// TIA Portal project "SVC_Sample" (V13)

(* hardware
DEVICE "S7-1200-Station_1"  S7-1200 Station
   slot 0: "Baugruppenträger_0"  Rack  V1.0
   slot 1: "PLC_1"  CPU 1214C DC/DC/DC  6ES7 214-1AG40-0XB0  V4.1
DEVICE "S71500/ET200MP-Station_1"  S7-1500 station
   slot 0: "Profilschiene_0"  6ES7 590-1***0-0AA0
   slot 1: "PLC_2"  CPU 1513F-1 PN  6ES7 513-1FL00-0AB0  V1.7
DEVICE "GSD-Geraet_2"  GSD.Device.PN
   slot 0: "Baugruppenträger"  Rail  V1.0
   slot 0: "svc01"  BAE0103  V3.x
DEVICE "GSD-Geraet_1"  GSD.Device.PN
   slot 0: "Baugruppenträger"  Rail  V1.0
   slot 0: "svc01_1"  BAE0103  V3.x
*)

// ===== PLC "PLC_1"  CPU 1214C DC/DC/DC =====

VAR_GLOBAL   // PLC tag table "Standard-Variablentabelle"
   "System_Byte" AT %MB1 : Byte;
   "FirstScan" AT %M1.0 : Bool;
   "DiagStatusUpdate" AT %M1.1 : Bool;
   "AlwaysTRUE" AT %M1.2 : Bool;
   "AlwaysFALSE" AT %M1.3 : Bool;
   "Clock_Byte" AT %MB0 : Byte;
   "Clock_10Hz" AT %M0.0 : Bool;
   "Clock_5Hz" AT %M0.1 : Bool;
   "Clock_2.5Hz" AT %M0.2 : Bool;
   "Clock_2Hz" AT %M0.3 : Bool;
   "Clock_1.25Hz" AT %M0.4 : Bool;
   "Clock_1Hz" AT %M0.5 : Bool;
   "Clock_0.625Hz" AT %M0.6 : Bool;
   "Clock_0.5Hz" AT %M0.7 : Bool;
END_VAR

DATA_BLOCK "DB_BVS_SC"   // DB10
{ S7_Optimized_Access := 'FALSE' }
VERSION : 0.1
"Call_BVS_SC"
BEGIN
END_DATA_BLOCK

DATA_BLOCK "Cam_Input"   // DB31
{ S7_Optimized_Access := 'FALSE' }
VERSION : 0.1
   VAR
      SendByte : Array[0..3999] of Byte;
   END_VAR
BEGIN
END_DATA_BLOCK

DATA_BLOCK "Cam_Output"   // DB32
{ S7_Optimized_Access := 'FALSE' }
VERSION : 0.1
   VAR
      "n.u." : Byte;
      AppID : Byte;
      Brightness : Int;
      ReadBarcode : Array[0..255] of Char;
      CodePositionX : Real;
      BarcodeLocated : Byte;
   END_VAR
BEGIN
END_DATA_BLOCK

FUNCTION_BLOCK "Call_BVS_SC"   // FB10, FBD
TITLE = Calling example Smart Camera / Smart Vision Controller FB
{ S7_Optimized_Access := 'FALSE' }
VERSION : 0.1
// Example call for Smart Camera / Smart Vision Controller function block BVS_SC[FB50]
// ! Same functionblock FB 50 can be used for Smart Camera and Smart Vision Controller!
// 
// FB Inputs are assigned to static variables of "Call_BVS_SC[FB10]".
   VAR_TEMP   // added for the SCL form of the ladder/FBD networks
      _w1 : Bool;
   END_VAR
BEGIN

REGION Network 1: Set Defaults
   // Set the FB Inputs to default values 
   // The Cam_Default bit is set at PLC Startup [OB100].
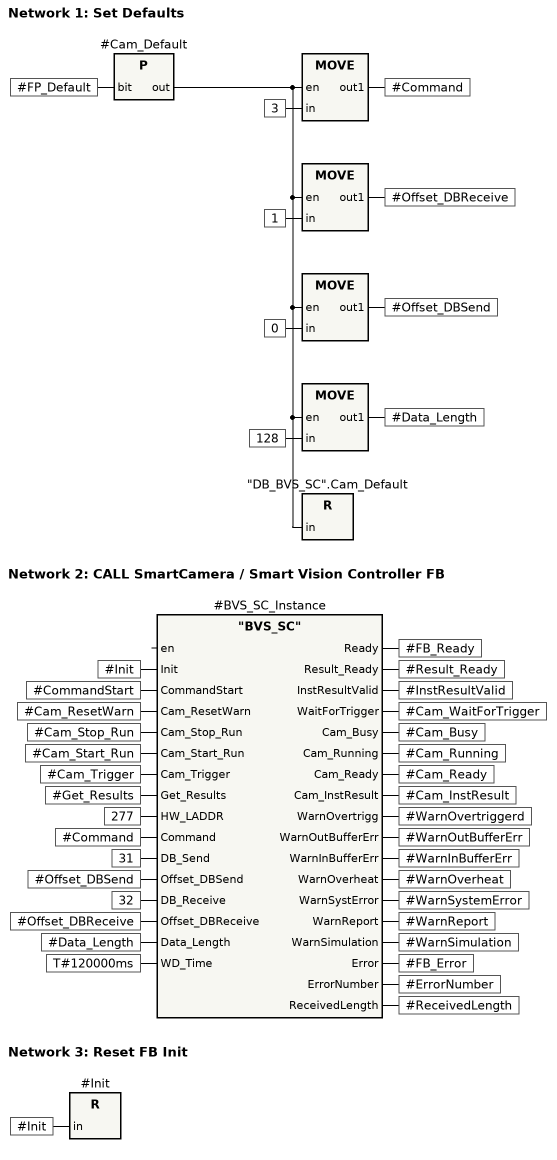
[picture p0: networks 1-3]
   #_w1 := #Cam_Default AND NOT #FP_Default;   // rising edge of #Cam_Default
   #FP_Default := #Cam_Default;
   IF #_w1 THEN
       #Command := 3;
       #Offset_DBReceive := 1;
       #Offset_DBSend := 0;
       #Data_Length := 128;
       "DB_BVS_SC".Cam_Default := FALSE;
   END_IF;
END_REGION

REGION Network 2: CALL SmartCamera / Smart Vision Controller FB
   // Multi instance call of SmartCamera function block. The abbreviation Cam_ is for "Camera" signals
   // 
   // Notice HW_Laddr! : Use assigned address from Devices & networks --> BVS-SC --> SmartCamera E/A 64/64 Byte --> 
   // properties--> HW Identifier.
   // 
   // Open the VAT_BVS-SC_IBN watch table for controlling the example
   // 
   // Cam_Stop / Start is changing the Camera Mode. The actual mode is displayed at Cam_Running output.
   // The FB ready output is true after FB Init and Camera startup.
   // If wait for trigger is true and busy is false, the camera is ready to receive trigger pulses.
   // SmartCamera commandos can be selected at the Command input.
   // Commads are executed by a rising edge at CommandStart input.
   // 
   // The camera result container is transmitted to Cam_Ouput[DB32] when Get_Results is true.
   // Data are send from Cam_Input[DB31] if Command 4 is executed.
   #BVS_SC_Instance(Init := #Init,   // "BVS_SC"
                    CommandStart := #CommandStart,
                    Cam_ResetWarn := #Cam_ResetWarn,
                    Cam_Stop_Run := #Cam_Stop_Run,
                    Cam_Start_Run := #Cam_Start_Run,
                    Cam_Trigger := #Cam_Trigger,
                    Get_Results := #Get_Results,
                    HW_LADDR := 277,
                    Command := #Command,
                    DB_Send := 31,
                    Offset_DBSend := #Offset_DBSend,
                    DB_Receive := 32,
                    Offset_DBReceive := #Offset_DBReceive,
                    Data_Length := #Data_Length,
                    WD_Time := T#120000ms,
                    Ready => #FB_Ready,
                    Result_Ready => #Result_Ready,
                    InstResultValid => #InstResultValid,
                    WaitForTrigger => #Cam_WaitForTrigger,
                    Cam_Busy => #Cam_Busy,
                    Cam_Running => #Cam_Running,
                    Cam_Ready => #Cam_Ready,
                    Cam_InstResult => #Cam_InstResult,
                    WarnOvertrigg => #WarnOvertriggerd,
                    WarnOutBufferErr => #WarnOutBufferErr,
                    WarnInBufferErr => #WarnInBufferErr,
                    WarnOverheat => #WarnOverheat,
                    WarnSystError => #WarnSystemError,
                    WarnReport => #WarnReport,
                    WarnSimulation => #WarnSimulation,
                    Error => #FB_Error,
                    ErrorNumber => #ErrorNumber,
                    ReceivedLength => #ReceivedLength);
END_REGION

REGION Network 3: Reset FB Init
   // Reset the Init bit after calling BVS_SC function block
   // The Init bit is set at PLC Startup [OB100]
   IF #Init THEN #Init := FALSE; END_IF;
END_REGION
END_FUNCTION_BLOCK

FUNCTION_BLOCK "BVS_SC"   // FB50, SCL
TITLE = BVS_SC
{ S7_Optimized_Access := 'FALSE' }
AUTHOR : BI-CU
FAMILY : Balluff
VERSION : 1.4
BEGIN
END_FUNCTION_BLOCK

ORGANIZATION_BLOCK "Main"   // OB1, FBD, ProgramCycle
TITLE = SVC Sampleprogram / "Main Program Sweep (Cycle)"
{ S7_Optimized_Access := 'FALSE' }
VERSION : 0.1
// Example for Smart Vision Controller
BEGIN

REGION Network 1: Call program example FB
   // Call the example program for one Camera connected to the Smart Vision Controller
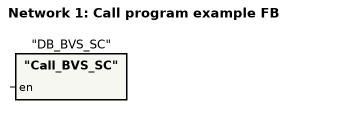
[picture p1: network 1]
   "DB_BVS_SC"();   // "Call_BVS_SC"
END_REGION
END_ORGANIZATION_BLOCK

ORGANIZATION_BLOCK "Startup"   // OB100, FBD, Startup
TITLE = "Complete Restart"
{ S7_Optimized_Access := 'FALSE' }
VERSION : 0.1
BEGIN

REGION Network 1: Internal reset and initailisation of FB
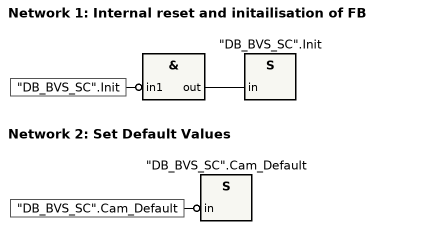
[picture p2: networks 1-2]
   IF NOT "DB_BVS_SC".Init THEN "DB_BVS_SC".Init := TRUE; END_IF;
END_REGION

REGION Network 2: Set Default Values
   IF NOT "DB_BVS_SC".Cam_Default THEN "DB_BVS_SC".Cam_Default := TRUE; END_IF;
END_REGION
END_ORGANIZATION_BLOCK

// ===== PLC "PLC_2"  CPU 1513F-1 PN =====

VAR_GLOBAL   // PLC tag table "Standard-Variablentabelle"
   "IOL_Port_Pin_2" AT %A2.0 : Bool;
   "S_Light_Seg1Bit0" AT %Q100.0 : Bool;   // Smart Light Segment 1
   "S_Light_Seg1Bit1" AT %Q100.1 : Bool;   // Smart Light Segment 1
   "S_Light_Seg1Bit2" AT %Q100.2 : Bool;   // Smart Light Segment 1
   "S_Light_Seg1Bit3" AT %Q100.3 : Bool;   // Smart Light Segment 1
   "S_Light_Seg3Bit0" AT %Q101.0 : Bool;   // Smart Light Segment 3
   "S_Light_Seg3Bit1" AT %Q101.1 : Bool;   // Smart Light Segment 3
   "S_Light_Seg3Bit2" AT %Q101.2 : Bool;   // Smart Light Segment 3
   "S_Light_Seg3Bit3" AT %Q101.3 : Bool;   // Smart Light Segment 3
   "S_Light_Seg2Bit0" AT %Q100.4 : Bool;   // Smart Light Segment 2
   "S_Light_Seg2Bit1" AT %Q100.5 : Bool;   // Smart Light Segment 2
   "S_Light_Seg2Bit2" AT %Q100.6 : Bool;   // Smart Light Segment 2
   "S_Light_Seg2Bit3" AT %Q100.7 : Bool;   // Smart Light Segment 2
   "System_Byte" AT %MB1 : Byte;
   "FirstScan" AT %M1.0 : Bool;
   "DiagStatusUpdate" AT %M1.1 : Bool;
   "AlwaysTRUE" AT %M1.2 : Bool;
   "AlwaysFALSE" AT %M1.3 : Bool;
   "Clock_Byte" AT %MB0 : Byte;
   "Clock_10Hz" AT %M0.0 : Bool;
   "Clock_5Hz" AT %M0.1 : Bool;
   "Clock_2.5Hz" AT %M0.2 : Bool;
   "Clock_2Hz" AT %M0.3 : Bool;
   "Clock_1.25Hz" AT %M0.4 : Bool;
   "Clock_1Hz" AT %M0.5 : Bool;
   "Clock_0.625Hz" AT %M0.6 : Bool;
   "Clock_0.5Hz" AT %M0.7 : Bool;
   "Tag_1" AT %E100.0 : Bool;
END_VAR

DATA_BLOCK "DB_BVS_SC"   // DB10
{ S7_Optimized_Access := 'FALSE' }
VERSION : 0.1
"Call_BVS_SC"
BEGIN
END_DATA_BLOCK

DATA_BLOCK "Cam_Input"   // DB31
{ S7_Optimized_Access := 'FALSE' }
VERSION : 0.1
   VAR
      SendByte : Array[0..3999] of Byte;
   END_VAR
BEGIN
END_DATA_BLOCK

DATA_BLOCK "Cam_Output"   // DB32
{ S7_Optimized_Access := 'FALSE' }
VERSION : 0.1
   VAR
      "n.u." : Byte;
      AppID : Byte;
      Brightness : Int;
      ReadBarcode : Array[0..255] of Char;
      CodePositionX : Real;
      BarcodeLocated : Byte;
   END_VAR
BEGIN
END_DATA_BLOCK

FUNCTION_BLOCK "Call_BVS_SC"   // FB10, FBD
TITLE = Calling example Smart Camera / Smart Vision Controller FB
{ S7_Optimized_Access := 'FALSE' }
VERSION : 0.1
// Example call for Smart Camera / Smart Vision Controller function block BVS_SC[FB50]
// ! Same functionblock FB 50 can be used for Smart Camera and Smart Vision Controller!
// 
// FB Inputs are assigned to static variables of "Call_BVS_SC[FB10]".
   VAR_TEMP   // added for the SCL form of the ladder/FBD networks
      _w1 : Bool;
   END_VAR
BEGIN

REGION Network 1: Set Defaults
   // Set the FB Inputs to default values 
   // The Cam_Default bit is set at PLC Startup [OB100].
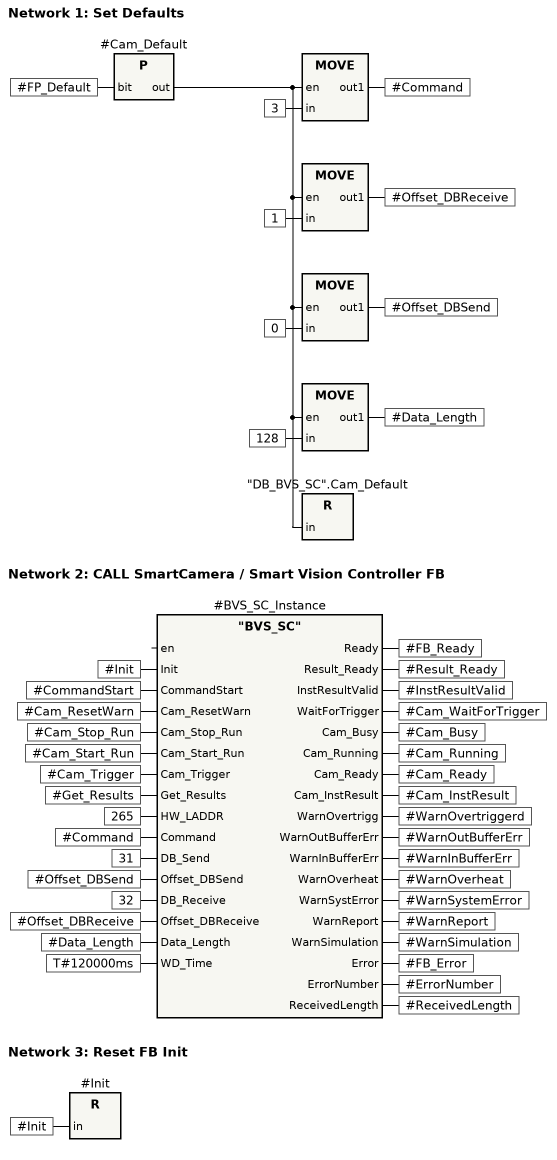
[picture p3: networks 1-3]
   #_w1 := #Cam_Default AND NOT #FP_Default;   // rising edge of #Cam_Default
   #FP_Default := #Cam_Default;
   IF #_w1 THEN
       #Command := 3;
       #Offset_DBReceive := 1;
       #Offset_DBSend := 0;
       #Data_Length := 128;
       "DB_BVS_SC".Cam_Default := FALSE;
   END_IF;
END_REGION

REGION Network 2: CALL SmartCamera / Smart Vision Controller FB
   // Multi instance call of SmartCamera function block. The abbreviation Cam_ is for "Camera" signals
   // 
   // Notice HW_Laddr! : Use assigned address from Devices & networks --> BVS-SC --> SmartCamera E/A 64/64 Byte --> 
   // properties--> HW Identifier.
   // 
   // Open the VAT_BVS-SC_IBN watch table for controlling the example
   // 
   // Cam_Stop / Start is changing the Camera Mode. The actual mode is displayed at Cam_Running output.
   // The FB ready output is true after FB Init and Camera startup.
   // If wait for trigger is true and busy is false, the camera is ready to receive trigger pulses.
   // SmartCamera commandos can be selected at the Command input.
   // Commads are executed by a rising edge at CommandStart input.
   // 
   // The camera result container is transmitted to Cam_Ouput[DB32] when Get_Results is true.
   // Data are send from Cam_Input[DB31] if Command 4 is executed.
   #BVS_SC_Instance(Init := #Init,   // "BVS_SC"
                    CommandStart := #CommandStart,
                    Cam_ResetWarn := #Cam_ResetWarn,
                    Cam_Stop_Run := #Cam_Stop_Run,
                    Cam_Start_Run := #Cam_Start_Run,
                    Cam_Trigger := #Cam_Trigger,
                    Get_Results := #Get_Results,
                    HW_LADDR := 265,
                    Command := #Command,
                    DB_Send := 31,
                    Offset_DBSend := #Offset_DBSend,
                    DB_Receive := 32,
                    Offset_DBReceive := #Offset_DBReceive,
                    Data_Length := #Data_Length,
                    WD_Time := T#120000ms,
                    Ready => #FB_Ready,
                    Result_Ready => #Result_Ready,
                    InstResultValid => #InstResultValid,
                    WaitForTrigger => #Cam_WaitForTrigger,
                    Cam_Busy => #Cam_Busy,
                    Cam_Running => #Cam_Running,
                    Cam_Ready => #Cam_Ready,
                    Cam_InstResult => #Cam_InstResult,
                    WarnOvertrigg => #WarnOvertriggerd,
                    WarnOutBufferErr => #WarnOutBufferErr,
                    WarnInBufferErr => #WarnInBufferErr,
                    WarnOverheat => #WarnOverheat,
                    WarnSystError => #WarnSystemError,
                    WarnReport => #WarnReport,
                    WarnSimulation => #WarnSimulation,
                    Error => #FB_Error,
                    ErrorNumber => #ErrorNumber,
                    ReceivedLength => #ReceivedLength);
END_REGION

REGION Network 3: Reset FB Init
   // Reset the Init bit after calling BVS_SC function block
   // The Init bit is set at PLC Startup [OB100]
   IF #Init THEN #Init := FALSE; END_IF;
END_REGION
END_FUNCTION_BLOCK

FUNCTION_BLOCK "BVS_SC"   // FB50, SCL
TITLE = BVS_SC
{ S7_Optimized_Access := 'FALSE' }
AUTHOR : BI-CU
FAMILY : Balluff
VERSION : 1.4
BEGIN
END_FUNCTION_BLOCK

ORGANIZATION_BLOCK "Main"   // OB1, FBD, ProgramCycle
TITLE = SVC Sampleprogram / "Main Program Sweep (Cycle)"
{ S7_Optimized_Access := 'FALSE' }
VERSION : 0.1
// Example for Smart Vision Controller
BEGIN

REGION Network 1: Call program example FB
   // Call the example program for one Camera connected to the Smart Vision Controller
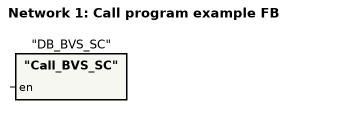
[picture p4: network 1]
   "DB_BVS_SC"();   // "Call_BVS_SC"
END_REGION
END_ORGANIZATION_BLOCK

ORGANIZATION_BLOCK "Startup"   // OB100, FBD, Startup
TITLE = "Complete Restart"
{ S7_Optimized_Access := 'FALSE' }
VERSION : 0.1
BEGIN

REGION Network 1: Internal reset and initailisation of FB
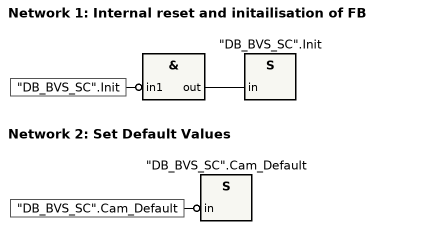
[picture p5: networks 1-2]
   IF NOT "DB_BVS_SC".Init THEN "DB_BVS_SC".Init := TRUE; END_IF;
END_REGION

REGION Network 2: Set Default Values
   IF NOT "DB_BVS_SC".Cam_Default THEN "DB_BVS_SC".Cam_Default := TRUE; END_IF;
END_REGION
END_ORGANIZATION_BLOCK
